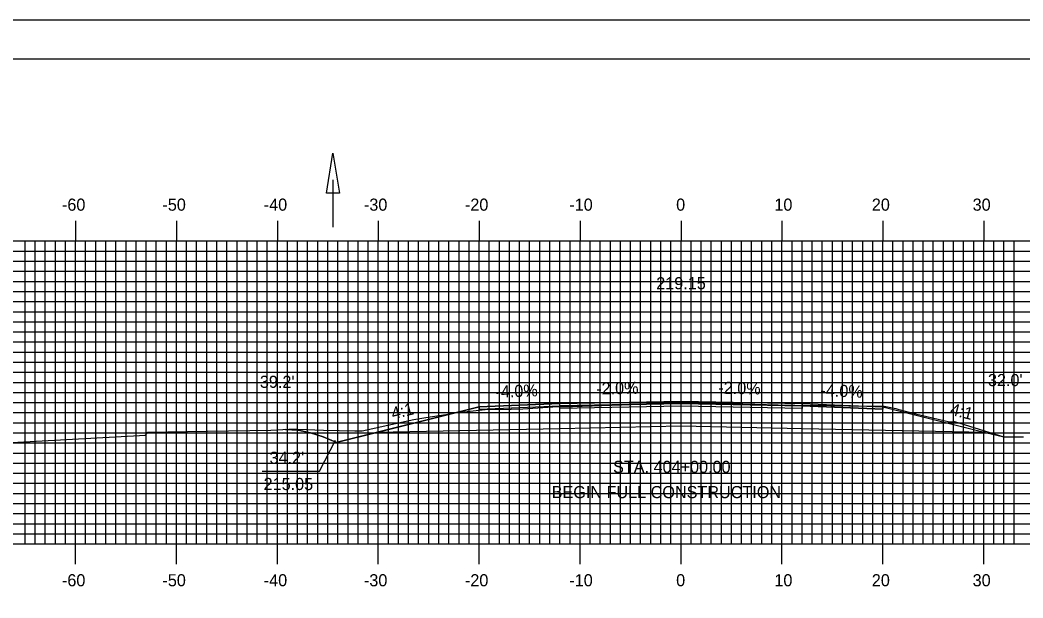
# Model space of a CAD drawing. Extents: x 850955 to 851298, y 364785 to 365005.
# Drawn here: x 851055.2 to 851154.6, y 364947.9 to 365005.1 of the extents above; entities that cross this region are included whole.
import ezdxf

# ---------------------------------------------------------------- set-up
doc = ezdxf.new("R2010")
doc.units = 0
for name, color, linetype in [('ANNOTATION', 7, 'Continuous'), ('BORDER', 7, 'Continuous'), ('D_Drainage_Ditch_Line', 7, 'Continuous'), ('D_Roadway_Centerline', 7, 'Continuous'), ('D_Roadway_Centerline_Text', 7, 'Continuous'), ('D_Roadway_Edge_Shoulder', 7, 'Continuous'), ('D_Roadway_Edge_TW', 7, 'Continuous'), ('D_Roadway_Pavement', 7, 'Continuous'), ('D_Roadway_SlopeLines', 7, 'Continuous'), ('D_Roadway_SubGrade', 7, 'Continuous'), ('D_Text_Standard', 7, 'Continuous'), ('H_V ANNOTATION', 7, 'Continuous'), ('MAJOR', 7, 'Continuous'), ('MINOR', 7, 'Continuous'), ('PLOT BOUNDARY', 7, 'Continuous'), ('S_Roadway_Centerline', 7, 'Continuous')]:
    doc.layers.add(name, color=color, linetype=linetype)

msp = doc.modelspace()

# ---------------------------------------------------------------- linework, layer by layer
at = {"layer": 'ANNOTATION'}
msp.add_lwpolyline([(851079.167, 364960.44), (851084.858, 364960.44), (851086.425, 364963.498)], dxfattribs=at)
at = {"layer": 'BORDER'}
msp.add_lwpolyline([(850971.078, 364791.233), (851291.078, 364791.233), (851291.078, 365001.233), (850971.078, 365001.233)], close=True, dxfattribs=at)
at = {"layer": 'D_Drainage_Ditch_Line'}
msp.add_line((851086.186, 364989.293), (851086.186, 364984.594), dxfattribs=at)
msp.add_lwpolyline([(851086.842, 364987.981), (851085.53, 364987.981), (851086.186, 364991.918)], close=True, dxfattribs=at)
at = {"layer": 'D_Roadway_Centerline'}
msp.add_lwpolyline([(851081.476, 364964.579), (851082.726, 364964.485), (851083.976, 364964.24), (851085.226, 364963.843), (851086.476, 364963.294), (851086.504, 364963.28), (851090.504, 364964.28), (851100.678, 364966.823), (851108.678, 364967.143), (851120.678, 364967.383), (851132.678, 364967.143), (851140.678, 364966.823), (851150.852, 364964.28), (851152.663, 364963.827)], dxfattribs=at)
at = {"layer": 'D_Roadway_Edge_Shoulder'}
for points in [[(851108.678, 364967.143), (851100.678, 364966.823), (851100.678, 364966.573), (851108.678, 364966.893)], [(851132.678, 364967.143), (851140.678, 364966.823), (851140.678, 364966.573), (851132.678, 364966.893)]]:
    msp.add_lwpolyline(points, close=True, dxfattribs=at)
at = {"layer": 'D_Roadway_Edge_TW'}
msp.add_lwpolyline([(851108.678, 364966.893), (851108.678, 364967.143), (851120.678, 364967.383), (851132.678, 364967.143), (851132.678, 364966.893), (851120.678, 364967.133)], close=True, dxfattribs=at)
at = {"layer": 'D_Roadway_Pavement'}
msp.add_lwpolyline([(851108.678, 364966.643), (851108.678, 364966.893), (851120.678, 364967.133), (851132.678, 364966.893), (851132.678, 364966.643), (851120.678, 364966.883)], close=True, dxfattribs=at)
at = {"layer": 'D_Roadway_SlopeLines'}
msp.add_line((851152.154, 364963.954), (851152.663, 364963.827), dxfattribs=at)
for points in [[(851100.678, 364966.823), (851086.504, 364963.28)], [(851086.504, 364963.28), (851086.476, 364963.294), (851085.226, 364963.843), (851083.976, 364964.24), (851082.726, 364964.485), (851081.476, 364964.579)]]:
    msp.add_lwpolyline(points, dxfattribs=at)
at = {"layer": 'D_Roadway_SubGrade'}
msp.add_lwpolyline([(851108.678, 364964.643), (851090.504, 364964.28), (851100.678, 364966.823), (851100.678, 364966.573), (851108.678, 364966.893), (851120.678, 364967.133), (851132.678, 364966.893), (851140.678, 364966.573), (851140.678, 364966.823), (851150.852, 364964.28), (851132.678, 364964.643), (851120.678, 364964.883)], close=True, dxfattribs=at)
at = {"layer": 'MAJOR'}
for p, q in [((851060.678, 364985.237), (851060.678, 364983.233)), ((851070.678, 364985.237), (851070.678, 364983.233)), ((851080.678, 364985.237), (851080.678, 364983.233)), ((851090.678, 364985.237), (851090.678, 364983.233)), ((851100.678, 364985.237), (851100.678, 364983.233)), ((851110.678, 364985.237), (851110.678, 364983.233)), ((851120.678, 364985.237), (851120.678, 364983.233)), ((851130.678, 364985.237), (851130.678, 364983.233)), ((851140.678, 364985.237), (851140.678, 364983.233)), ((851150.678, 364985.237), (851150.678, 364983.233)), ((850980.678, 364983.233), (851260.678, 364983.233)), ((850980.678, 364983.233), (851260.678, 364983.233)), ((851060.678, 364953.233), (851060.678, 364983.233)), ((851070.678, 364953.233), (851070.678, 364983.233)), ((851080.678, 364953.233), (851080.678, 364983.233)), ((851090.678, 364953.233), (851090.678, 364983.233)), ((851100.678, 364953.233), (851100.678, 364983.233)), ((851110.678, 364953.233), (851110.678, 364983.233)), ((851120.678, 364953.233), (851120.678, 364983.233)), ((851130.678, 364953.233), (851130.678, 364983.233)), ((851140.678, 364953.233), (851140.678, 364983.233)), ((851150.678, 364953.233), (851150.678, 364983.233)), ((850980.678, 364978.233), (851260.678, 364978.233)), ((850980.678, 364973.233), (851260.678, 364973.233)), ((850980.678, 364968.233), (851260.678, 364968.233)), ((850980.678, 364963.233), (851260.678, 364963.233)), ((850980.678, 364958.233), (851260.678, 364958.233)), ((850980.678, 364953.233), (851260.678, 364953.233)), ((850980.678, 364953.233), (851260.678, 364953.233)), ((851060.678, 364951.229), (851060.678, 364953.233)), ((851070.678, 364951.229), (851070.678, 364953.233)), ((851080.678, 364951.229), (851080.678, 364953.233)), ((851090.678, 364951.229), (851090.678, 364953.233)), ((851100.678, 364951.229), (851100.678, 364953.233)), ((851110.678, 364951.229), (851110.678, 364953.233)), ((851120.678, 364951.229), (851120.678, 364953.233)), ((851130.678, 364951.229), (851130.678, 364953.233)), ((851140.678, 364951.229), (851140.678, 364953.233)), ((851150.678, 364951.229), (851150.678, 364953.233))]:
    msp.add_line(p, q, dxfattribs=at)
at = {"layer": 'MINOR'}
for p, q in [((851055.678, 364953.233), (851055.678, 364983.233)), ((851056.678, 364953.233), (851056.678, 364983.233)), ((851057.678, 364953.233), (851057.678, 364983.233)), ((851058.678, 364953.233), (851058.678, 364983.233)), ((851059.678, 364953.233), (851059.678, 364983.233)), ((851061.678, 364953.233), (851061.678, 364983.233)), ((851062.678, 364953.233), (851062.678, 364983.233)), ((851063.678, 364953.233), (851063.678, 364983.233)), ((851064.678, 364953.233), (851064.678, 364983.233)), ((851065.678, 364953.233), (851065.678, 364983.233)), ((851066.678, 364953.233), (851066.678, 364983.233)), ((851067.678, 364953.233), (851067.678, 364983.233)), ((851068.678, 364953.233), (851068.678, 364983.233)), ((851069.678, 364953.233), (851069.678, 364983.233)), ((851071.678, 364953.233), (851071.678, 364983.233)), ((851072.678, 364953.233), (851072.678, 364983.233)), ((851073.678, 364953.233), (851073.678, 364983.233)), ((851074.678, 364953.233), (851074.678, 364983.233)), ((851075.678, 364953.233), (851075.678, 364983.233)), ((851076.678, 364953.233), (851076.678, 364983.233)), ((851077.678, 364953.233), (851077.678, 364983.233)), ((851078.678, 364953.233), (851078.678, 364983.233)), ((851079.678, 364953.233), (851079.678, 364983.233)), ((851081.678, 364953.233), (851081.678, 364983.233)), ((851082.678, 364953.233), (851082.678, 364983.233)), ((851083.678, 364953.233), (851083.678, 364983.233)), ((851084.678, 364953.233), (851084.678, 364983.233)), ((851085.678, 364953.233), (851085.678, 364983.233)), ((851086.678, 364953.233), (851086.678, 364983.233)), ((851087.678, 364953.233), (851087.678, 364983.233)), ((851088.678, 364953.233), (851088.678, 364983.233)), ((851089.678, 364953.233), (851089.678, 364983.233)), ((851091.678, 364953.233), (851091.678, 364983.233)), ((851092.678, 364953.233), (851092.678, 364983.233)), ((851093.678, 364953.233), (851093.678, 364983.233)), ((851094.678, 364953.233), (851094.678, 364983.233)), ((851095.678, 364953.233), (851095.678, 364983.233)), ((851096.678, 364953.233), (851096.678, 364983.233)), ((851097.678, 364953.233), (851097.678, 364983.233)), ((851098.678, 364953.233), (851098.678, 364983.233)), ((851099.678, 364953.233), (851099.678, 364983.233)), ((851101.678, 364953.233), (851101.678, 364983.233)), ((851102.678, 364953.233), (851102.678, 364983.233)), ((851103.678, 364953.233), (851103.678, 364983.233)), ((851104.678, 364953.233), (851104.678, 364983.233)), ((851105.678, 364953.233), (851105.678, 364983.233)), ((851106.678, 364953.233), (851106.678, 364983.233)), ((851107.678, 364953.233), (851107.678, 364983.233)), ((851108.678, 364953.233), (851108.678, 364983.233)), ((851109.678, 364953.233), (851109.678, 364983.233)), ((851111.678, 364953.233), (851111.678, 364983.233)), ((851112.678, 364953.233), (851112.678, 364983.233)), ((851113.678, 364953.233), (851113.678, 364983.233)), ((851114.678, 364953.233), (851114.678, 364983.233)), ((851115.678, 364953.233), (851115.678, 364983.233)), ((851116.678, 364953.233), (851116.678, 364983.233)), ((851117.678, 364953.233), (851117.678, 364983.233)), ((851118.678, 364953.233), (851118.678, 364983.233)), ((851119.678, 364953.233), (851119.678, 364983.233)), ((851121.678, 364953.233), (851121.678, 364983.233)), ((851122.678, 364953.233), (851122.678, 364983.233)), ((851123.678, 364953.233), (851123.678, 364983.233)), ((851124.678, 364953.233), (851124.678, 364983.233)), ((851125.678, 364953.233), (851125.678, 364983.233)), ((851126.678, 364953.233), (851126.678, 364983.233)), ((851127.678, 364953.233), (851127.678, 364983.233)), ((851128.678, 364953.233), (851128.678, 364983.233)), ((851129.678, 364953.233), (851129.678, 364983.233)), ((851131.678, 364953.233), (851131.678, 364983.233)), ((851132.678, 364953.233), (851132.678, 364983.233)), ((851133.678, 364953.233), (851133.678, 364983.233)), ((851134.678, 364953.233), (851134.678, 364983.233)), ((851135.678, 364953.233), (851135.678, 364983.233)), ((851136.678, 364953.233), (851136.678, 364983.233)), ((851137.678, 364953.233), (851137.678, 364983.233)), ((851138.678, 364953.233), (851138.678, 364983.233)), ((851139.678, 364953.233), (851139.678, 364983.233)), ((851141.678, 364953.233), (851141.678, 364983.233)), ((851142.678, 364953.233), (851142.678, 364983.233)), ((851143.678, 364953.233), (851143.678, 364983.233)), ((851144.678, 364953.233), (851144.678, 364983.233)), ((851145.678, 364953.233), (851145.678, 364983.233)), ((851146.678, 364953.233), (851146.678, 364983.233)), ((851147.678, 364953.233), (851147.678, 364983.233)), ((851148.678, 364953.233), (851148.678, 364983.233)), ((851149.678, 364953.233), (851149.678, 364983.233)), ((851151.678, 364953.233), (851151.678, 364983.233)), ((851152.678, 364953.233), (851152.678, 364983.233)), ((851153.678, 364953.233), (851153.678, 364983.233)), ((850980.678, 364982.233), (851260.678, 364982.233)), ((850980.678, 364981.233), (851260.678, 364981.233)), ((850980.678, 364980.233), (851260.678, 364980.233)), ((850980.678, 364979.233), (851260.678, 364979.233)), ((850980.678, 364977.233), (851260.678, 364977.233)), ((850980.678, 364976.233), (851260.678, 364976.233)), ((850980.678, 364975.233), (851260.678, 364975.233)), ((850980.678, 364974.233), (851260.678, 364974.233)), ((850980.678, 364972.233), (851260.678, 364972.233)), ((850980.678, 364971.233), (851260.678, 364971.233)), ((850980.678, 364970.233), (851260.678, 364970.233)), ((850980.678, 364969.233), (851260.678, 364969.233)), ((850980.678, 364967.233), (851260.678, 364967.233)), ((850980.678, 364966.233), (851260.678, 364966.233)), ((850980.678, 364965.233), (851260.678, 364965.233)), ((850980.678, 364964.233), (851260.678, 364964.233)), ((850980.678, 364962.233), (851260.678, 364962.233)), ((850980.678, 364961.233), (851260.678, 364961.233)), ((850980.678, 364960.233), (851260.678, 364960.233)), ((850980.678, 364959.233), (851260.678, 364959.233)), ((850980.678, 364957.233), (851260.678, 364957.233)), ((850980.678, 364956.233), (851260.678, 364956.233)), ((850980.678, 364955.233), (851260.678, 364955.233)), ((850980.678, 364954.233), (851260.678, 364954.233))]:
    msp.add_line(p, q, dxfattribs=at)
at = {"layer": 'PLOT BOUNDARY'}
msp.add_lwpolyline([(850954.892, 364785.114), (851294.892, 364785.114), (851294.892, 365005.114), (850954.892, 365005.114)], close=True, dxfattribs=at)
at = {"layer": 'S_Roadway_Centerline'}
msp.add_lwpolyline([(851051.924, 364963.136), (851067.625, 364963.992), (851067.827, 364964.295), (851073.738, 364964.409), (851080.03, 364964.485), (851081.821, 364964.601), (851082.72, 364964.58), (851085.261, 364964.507), (851088.363, 364964.445), (851089.09, 364964.428), (851091.621, 364964.988), (851094.21, 364965.544), (851095.374, 364965.735), (851097.357, 364966.053), (851098.192, 364966.224), (851099.492, 364966.347), (851101.274, 364966.547), (851103.839, 364966.569), (851104.986, 364966.611), (851107.961, 364966.813), (851109.907, 364966.857), (851117.672, 364967.101), (851117.998, 364967.106), (851118.993, 364967.154), (851120.616, 364967.335), (851124.474, 364967.183), (851130.291, 364967.003), (851133.623, 364966.936), (851133.694, 364966.964), (851137.296, 364966.92), (851140.82, 364966.874), (851141.967, 364966.653), (851142.263, 364966.555), (851143.919, 364966.126), (851147.299, 364965.314), (851147.771, 364965.348), (851149.268, 364964.909), (851152.663, 364963.827), (851153.684, 364963.835), (851154.619, 364963.824)], dxfattribs=at)

# ---------------------------------------------------------------- texts
at = {"layer": 'ANNOTATION'}
for s, rotation, p in [('-4.0%', 2.29061, (851102.31, 364967.69)), ('-2.0%', 1.14576, (851112.284, 364968.016)), ('-2.0%', 358.85424, (851124.364, 364968.11)), ('-4.0%', 357.70939, (851134.47, 364967.873)), ('4:1', 14.03624, (851092.127, 364965.547)), ('4:1', 345.96376, (851147.271, 364966.037))]:
    msp.add_text(s, height=1.2, rotation=rotation, dxfattribs=at).set_placement(p)
for s, p in [("34.2'", (851079.901, 364961.166)), ('215.05', (851079.313, 364958.566))]:
    msp.add_text(s, height=1.2, dxfattribs=at).set_placement(p)
at = {"layer": 'D_Roadway_Centerline'}
for s, p in [('C', (851120.673, 364967.383)), ('L', (851120.678, 364967.376))]:
    msp.add_text(s, height=0.0146, dxfattribs=at).set_placement(p)
at = {"layer": 'D_Roadway_Centerline_Text'}
msp.add_text('219.15', height=1.2, dxfattribs=at).set_placement((851118.223, 364978.452))
at = {"layer": 'D_Text_Standard'}
for s, p in [("39.2'", (851078.945, 364968.688)), ("32.0'", (851151.094, 364968.858)), ('STA. 404+00.00', (851113.943, 364960.264)), ('BEGIN FULL CONSTRUCTION', (851107.86, 364957.764))]:
    msp.add_text(s, height=1.2, dxfattribs=at).set_placement(p)
at = {"layer": 'H_V ANNOTATION'}
for s, p in [('-60', (851059.33, 364986.233)), ('-50', (851069.287, 364986.233)), ('-40', (851079.33, 364986.233)), ('-30', (851089.255, 364986.233)), ('-20', (851099.265, 364986.233)), ('-10', (851109.608, 364986.233)), ('0', (851120.196, 364986.233)), ('10', (851129.929, 364986.233)), ('20', (851139.586, 364986.233)), ('30', (851149.576, 364986.233)), ('-60', (851059.33, 364949.033)), ('-50', (851069.287, 364949.033)), ('-40', (851079.33, 364949.033)), ('-30', (851089.255, 364949.033)), ('-20', (851099.265, 364949.033)), ('-10', (851109.608, 364949.033)), ('0', (851120.196, 364949.033)), ('10', (851129.929, 364949.033)), ('20', (851139.586, 364949.033)), ('30', (851149.576, 364949.033))]:
    msp.add_text(s, height=1.2, dxfattribs=at).set_placement(p)
at = {"layer": 'S_Roadway_Centerline'}
for s, p in [('L', (851120.607, 364967.328)), ('C', (851120.611, 364967.335))]:
    msp.add_text(s, height=0.0146, dxfattribs=at).set_placement(p)

doc.saveas('drawing.dxf')
